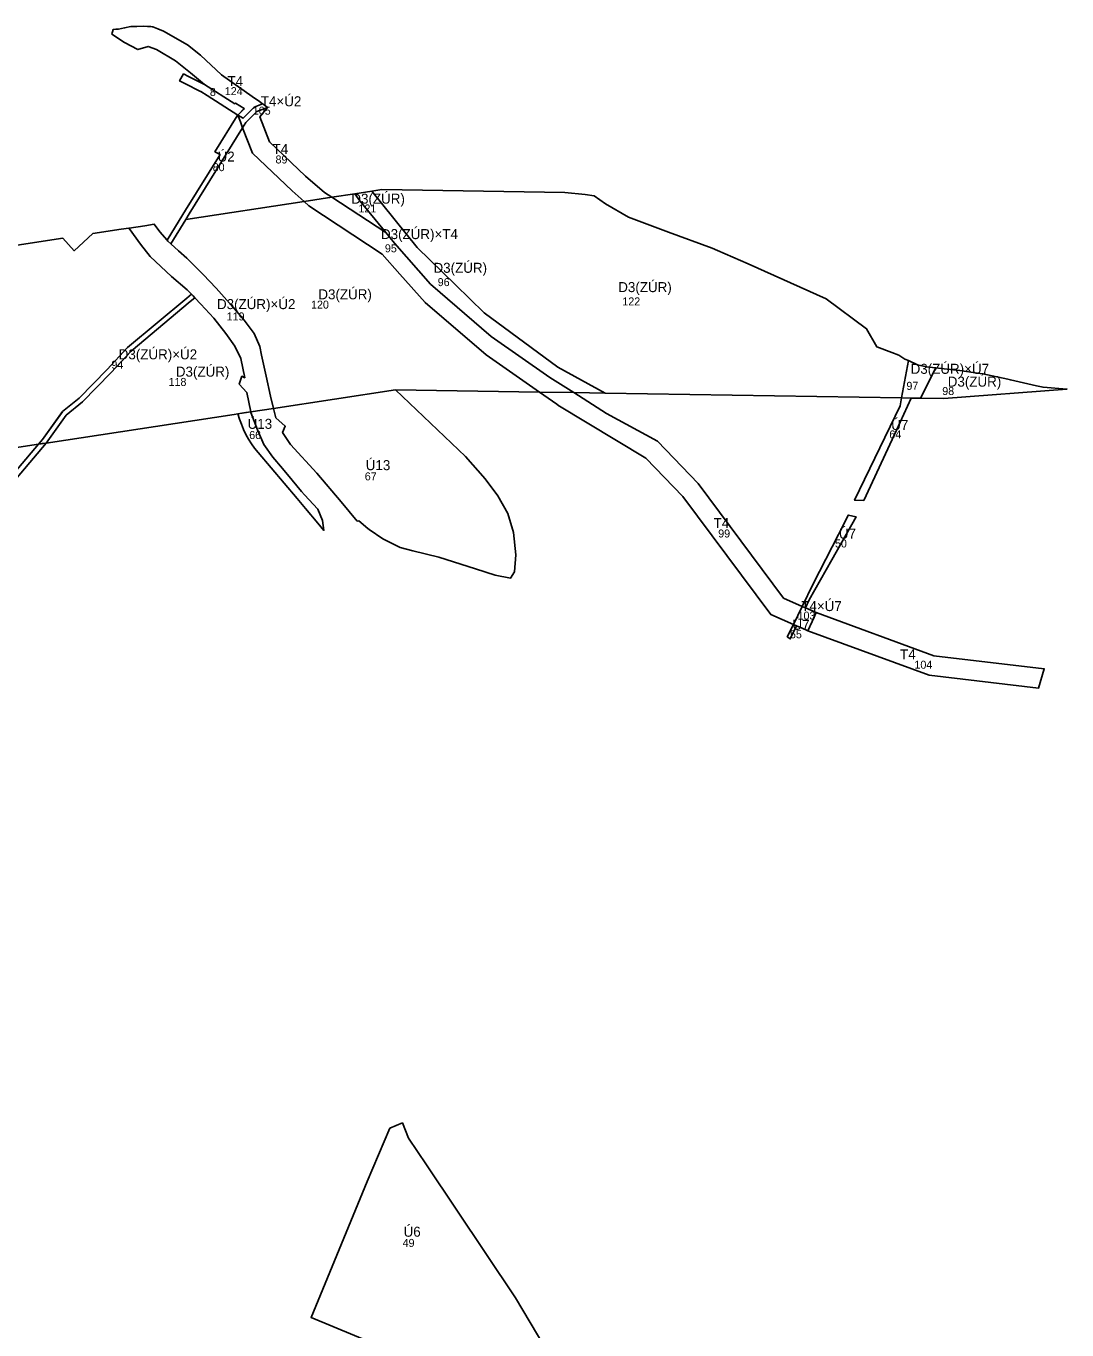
# Model space of a CAD drawing. Extents: x -521621 to -516857, y -1190025 to -1185894.
# Drawn here: x -518471 to -517431, y -1188636 to -1187332 of the extents above; entities that cross this region are included whole.
import ezdxf

# ---------------------------------------------------------------- set-up
doc = ezdxf.new("R2010")
doc.units = 0
for name, color, linetype in [('predk_pravo_n', 7, 'Continuous'), ('VPO_id', 7, 'Continuous'), ('VPO_n', 7, 'Continuous'), ('VPS_id', 7, 'Continuous'), ('VPS_n', 7, 'Continuous')]:
    doc.layers.add(name, color=color, linetype=linetype)

msp = doc.modelspace()

# ---------------------------------------------------------------- linework, layer by layer
at = {"layer": 'predk_pravo_n'}
msp.add_lwpolyline([(-518262.4, -1187410.1), (-518261.7, -1187409.4), (-518253.1, -1187414.9), (-518259.5, -1187421.5), (-518290.1, -1187402), (-518296.3, -1187398), (-518296.7, -1187397.8), (-518312.4, -1187389.9), (-518317.7, -1187387.2), (-518313.6, -1187380.3), (-518308.6, -1187382.8), (-518292.7, -1187390.8)], close=True, dxfattribs=at)
at = {"layer": 'VPO_n'}
msp.add_line((-518259.3, -1187720.1), (-518251.5, -1187718.9), dxfattribs=at)
for points in [[(-518256.9, -1187428.3), (-518259.5, -1187421.5), (-518260.1, -1187422.1), (-518282.4, -1187458), (-518277.2, -1187460.9), (-518311.7, -1187516.6), (-518318, -1187526.7), (-518330.2, -1187546.5), (-518329.5, -1187547.4), (-518326.5, -1187550.1), (-518311.5, -1187525.7), (-518308.1, -1187520.3), (-518254.7, -1187434.1), (-518256.9, -1187428.3)], [(-517981.5, -1187861.2), (-517984, -1187838.7), (-517989.8, -1187819.8), (-517999.6, -1187802), (-518012.2, -1187785.1), (-518031.8, -1187762.8), (-518102, -1187696.1), (-518223.7, -1187714.7), (-518221.4, -1187724), (-518212.1, -1187732.3), (-518214.8, -1187738.7), (-518206.7, -1187750.6), (-518180.6, -1187779.3), (-518156.2, -1187808.2), (-518140.1, -1187827.4), (-518138.5, -1187827.1), (-518129.6, -1187834.7), (-518128.2, -1187835.9), (-518114.6, -1187845), (-518097.1, -1187853.8), (-518084.7, -1187856.9), (-518058.6, -1187863.4), (-518021.9, -1187875.1), (-518002.4, -1187881.3), (-517987, -1187884.5), (-517982.9, -1187878.1), (-517981.5, -1187861.2)], [(-518251.5, -1187718.9), (-518246.6, -1187718.2), (-518246.4, -1187718.8), (-518239.9, -1187736), (-518233.5, -1187750.6), (-518224.4, -1187763.4), (-518214.8, -1187774.7), (-518205.2, -1187786.3), (-518195.8, -1187797.6), (-518192.9, -1187801.1), (-518179.6, -1187815.4), (-518174.7, -1187826.8), (-518173.4, -1187836.7), (-518179.5, -1187829.5), (-518191.9, -1187814.8), (-518200.3, -1187804.9), (-518239.2, -1187758.9)], [(-517695.5, -1187912.6), (-517684.5, -1187890.1), (-517652.7, -1187828.4), (-517649.4, -1187821.4), (-517641.6, -1187823), (-517665.7, -1187866.1), (-517688.4, -1187906.2), (-517692.2, -1187914)], [(-517692.2, -1187914), (-517695.5, -1187912.6)], [(-517701, -1187932), (-517707.4, -1187945.2), (-517710.4, -1187943), (-517704.3, -1187930.6)], [(-517704.3, -1187930.6), (-517701, -1187932)]]:
    msp.add_lwpolyline(points, dxfattribs=at)
for points in [[(-517633.7, -1187806.7), (-517643.1, -1187806.5), (-517597.6, -1187712.2), (-517596.1, -1187704.1), (-517586.4, -1187704.3), (-517601.2, -1187736.4)], [(-518451.1, -1187749.3), (-518518.3, -1187828.7), (-518530, -1187850.3), (-518533.4, -1187846), (-518522.5, -1187825.9), (-518458.6, -1187750.5)], [(-518107.5, -1188434.2), (-518094.9, -1188429), (-518088.8, -1188444.4), (-518071, -1188471), (-517982, -1188604), (-517899.2, -1188742.7), (-518042.7, -1188683.1), (-518186.2, -1188623.6), (-518130.3, -1188487.5)]]:
    msp.add_lwpolyline(points, close=True, dxfattribs=at)
msp.add_arc((-518164.4, -1187695.6), 98, 194.4563, 220.234, dxfattribs=at)
at = {"layer": 'VPS_n'}
for points in [[(-518306.6, -1187379.1), (-518292.7, -1187390.8), (-518262.4, -1187410.1), (-518261.7, -1187409.4), (-518253.1, -1187414.9), (-518253.9, -1187415.7), (-518259.5, -1187421.5), (-518254.2, -1187424.6), (-518248.7, -1187419), (-518243.2, -1187413.5), (-518234.7, -1187410.2), (-518237.9, -1187407.9), (-518245, -1187402.9), (-518275.7, -1187381.1), (-518296.7, -1187361.5), (-518309.7, -1187351.1), (-518333.6, -1187337.4), (-518339.3, -1187335.3), (-518344.5, -1187333.3), (-518345, -1187333.1), (-518346.4, -1187333), (-518349.6, -1187332.8), (-518354.1, -1187332.4), (-518360.3, -1187332.7), (-518366.5, -1187332.9), (-518372.6, -1187334.2), (-518378.8, -1187335.5), (-518381.4, -1187335.6), (-518384, -1187335.7), (-518384.7, -1187338.1), (-518385, -1187339.1), (-518385.4, -1187340.4), (-518372.8, -1187348.8), (-518359.5, -1187355.9), (-518349.2, -1187352.8), (-518340.9, -1187355.7), (-518321.7, -1187367.1), (-518306.6, -1187379.1)], [(-518240.4, -1187417.7), (-518229.8, -1187413.7), (-518232.2, -1187411.9), (-518234.7, -1187410.2), (-518243.2, -1187413.5), (-518248.7, -1187419), (-518254.2, -1187424.6), (-518259.5, -1187421.5), (-518256.9, -1187428.3), (-518254.7, -1187434.1), (-518251.4, -1187428.9), (-518244.4, -1187421.8), (-518240.4, -1187417.7)], [(-518240.4, -1187417.7), (-518244.4, -1187421.8), (-518251.4, -1187428.9), (-518254.7, -1187434.1), (-518244.8, -1187459.6), (-518205.2, -1187497.2), (-518193.2, -1187507.7), (-518165.5, -1187503.5), (-518172.9, -1187498.9), (-518191.7, -1187482.4), (-518227.7, -1187448.2), (-518237.5, -1187423), (-518229.8, -1187413.7), (-518240.4, -1187417.7)], [(-518223.7, -1187714.7), (-518102, -1187696.1), (-517958.1, -1187698.4), (-518011.3, -1187661), (-518072.1, -1187608.7), (-518097.5, -1187580.5), (-518115.1, -1187560.4), (-518188.5, -1187512.3), (-518193.2, -1187507.7), (-518311.5, -1187525.7), (-518326.5, -1187550.1), (-518318.7, -1187557.1), (-518310.4, -1187564.3), (-518294.1, -1187580.8), (-518281, -1187594.4), (-518267.8, -1187609.4), (-518266.5, -1187610.8), (-518253.1, -1187626.6), (-518243.1, -1187639.9), (-518237.5, -1187652.9), (-518235.9, -1187661.6), (-518231.2, -1187682.4), (-518226.7, -1187702.5), (-518223.7, -1187714.7)], [(-518142.6, -1187500), (-518165.5, -1187503.5), (-518111.5, -1187538.9), (-518137.5, -1187507.1), (-518142.6, -1187500)], [(-518142.6, -1187500), (-518137.5, -1187507.1), (-518111.5, -1187538.9), (-518102.9, -1187549.4), (-518067, -1187590.4), (-518006.3, -1187642.7), (-517947.8, -1187683.7), (-517923.8, -1187698.9), (-517892.4, -1187699.4), (-517939.8, -1187673.3), (-518013.4, -1187619.1), (-518042.1, -1187591.1), (-518080.2, -1187553.9), (-518125.5, -1187497.4), (-518142.6, -1187500)], [(-517939.8, -1187673.3), (-517892.4, -1187699.4), (-517596.1, -1187704.1), (-517589.2, -1187666.9), (-517592.8, -1187665.3), (-517598.9, -1187661.5), (-517606, -1187658.8), (-517620.9, -1187653.2), (-517631.2, -1187635), (-517671.4, -1187605.2), (-517749.3, -1187570.2), (-517780, -1187556.7), (-517785.5, -1187554.6), (-517829, -1187538.4), (-517869.1, -1187523.4), (-517892, -1187510.1), (-517903.3, -1187502.1), (-517912.3, -1187500.7), (-517932.8, -1187498.8), (-518115.5, -1187495.9), (-518125.5, -1187497.4), (-518080.2, -1187553.9), (-518042.1, -1187591.1), (-518013.4, -1187619.1), (-517939.8, -1187673.3)], [(-518614.8, -1187572), (-518434.3, -1187544.5), (-518423, -1187557), (-518404.5, -1187539.9), (-518376.1, -1187535.6), (-518368.5, -1187534.4), (-518367.9, -1187534.7), (-518356.8, -1187550.6), (-518347, -1187562.8), (-518336.4, -1187572.9), (-518325.6, -1187582.7), (-518310, -1187596), (-518305.9, -1187600.4), (-518310.5, -1187604.3), (-518369.6, -1187653.8), (-518390.1, -1187675.7), (-518418.1, -1187704.4), (-518434.6, -1187717.9), (-518454.6, -1187745.7), (-518458.6, -1187750.5), (-518594.2, -1187771.1)], [(-518318.7, -1187557.1), (-518326.5, -1187550.1), (-518329.5, -1187547.4), (-518330.2, -1187546.5), (-518337.4, -1187538), (-518343, -1187530.5), (-518352.3, -1187532), (-518368.1, -1187534.4), (-518367.9, -1187534.7), (-518356.8, -1187550.6), (-518347, -1187562.8), (-518336.4, -1187572.9), (-518325.6, -1187582.7), (-518310, -1187596), (-518305.9, -1187600.4), (-518304.1, -1187602.2), (-518302.4, -1187604), (-518296.4, -1187610.4), (-518283.6, -1187624.5), (-518271.6, -1187639.8), (-518262.3, -1187652.3), (-518256.3, -1187664.8), (-518252.6, -1187684.1), (-518255.4, -1187682.6), (-518258, -1187690.3), (-518250.4, -1187698.8), (-518246.6, -1187718.2), (-518223.7, -1187714.7), (-518226.7, -1187702.5), (-518231.2, -1187682.4), (-518235.9, -1187661.6), (-518237.5, -1187652.9), (-518243.1, -1187639.9), (-518253.1, -1187626.6), (-518266.5, -1187610.8), (-518267.8, -1187609.4), (-518281, -1187594.4), (-518294.1, -1187580.8), (-518310.4, -1187564.3), (-518318.7, -1187557.1)], [(-518302.4, -1187604), (-518307, -1187607.8), (-518366.2, -1187657.5), (-518386.5, -1187679.2), (-518414.8, -1187708.1), (-518430.9, -1187721.3), (-518451.1, -1187749.3), (-518322.2, -1187729.7), (-518263.2, -1187720.7), (-518259.3, -1187720.1), (-518246.6, -1187718.2), (-518250.4, -1187698.8), (-518258, -1187690.3), (-518255.4, -1187682.6), (-518252.6, -1187684.1), (-518256.3, -1187664.8), (-518262.3, -1187652.3), (-518271.6, -1187639.8), (-518283.6, -1187624.5), (-518296.4, -1187610.4), (-518302.4, -1187604)], [(-517586.4, -1187704.3), (-517596.1, -1187704.1), (-517589.2, -1187666.9), (-517580.3, -1187671.2), (-517573, -1187672.9), (-517572.6, -1187673), (-517572, -1187673.1)], [(-517562, -1187674.2), (-517577.2, -1187704.4)], [(-517562, -1187674.2), (-517577.2, -1187704.4), (-517553.8, -1187704.8), (-517430.9, -1187695.3), (-517454.8, -1187693.5), (-517461.3, -1187692.1), (-517487.3, -1187686.2), (-517489.9, -1187685.6), (-517514.8, -1187680), (-517520.3, -1187679.3), (-517520.3, -1187679.3), (-517537.9, -1187676.9), (-517553.7, -1187675.1), (-517562, -1187674.2)], [(-517572, -1187673.1), (-517562, -1187674.2)], [(-517940.8, -1187710.5), (-517958.1, -1187698.4), (-517923.8, -1187698.9), (-517890.9, -1187719.9)], [(-517577.2, -1187704.4), (-517586.4, -1187704.3)], [(-517704.3, -1187930.6), (-517726.9, -1187920.7), (-517814.6, -1187802.6), (-517851.6, -1187764.3), (-517939.7, -1187711.3)], [(-517890.9, -1187719.9), (-517840.1, -1187747.4), (-517799.3, -1187789.7), (-517714, -1187904.5), (-517695.5, -1187912.6)], [(-517695.5, -1187912.6), (-517704.3, -1187930.6)], [(-517689.8, -1187936.9), (-517568.5, -1187981.4), (-517459.3, -1187994.2), (-517453.5, -1187975), (-517563.8, -1187961.9), (-517681.4, -1187918.8), (-517685.6, -1187927.8), (-517689.8, -1187936.9)]]:
    msp.add_lwpolyline(points, dxfattribs=at)
for points in [[(-518193.2, -1187507.7), (-518165.5, -1187503.5), (-518111.5, -1187538.9), (-518102.9, -1187549.4), (-518067, -1187590.4), (-518006.3, -1187642.7), (-517947.8, -1187683.7), (-517923.8, -1187698.9), (-517958.1, -1187698.4), (-518011.3, -1187661), (-518072.1, -1187608.7), (-518097.5, -1187580.5), (-518115.1, -1187560.4), (-518188.5, -1187512.3)], [(-518434.6, -1187717.9), (-518418.1, -1187704.4), (-518390.1, -1187675.7), (-518369.6, -1187653.8), (-518310.5, -1187604.3), (-518305.9, -1187600.4), (-518304.1, -1187602.2), (-518302.4, -1187604), (-518307, -1187607.8), (-518366.2, -1187657.5), (-518386.5, -1187679.2), (-518414.8, -1187708.1), (-518430.9, -1187721.3), (-518451.1, -1187749.3), (-518454.9, -1187749.9), (-518458.6, -1187750.5), (-518454.6, -1187745.7), (-518434.6, -1187718)], [(-517704.3, -1187930.6), (-517695.5, -1187912.6), (-517692.2, -1187914), (-517681.4, -1187918.8), (-517685.6, -1187927.8), (-517689.8, -1187936.9), (-517695.4, -1187934.5), (-517701, -1187932)]]:
    msp.add_lwpolyline(points, close=True, dxfattribs=at)
msp.add_arc((-517929.3, -1187694.1), 20, 234.944, 238.9499, dxfattribs=at)

# ---------------------------------------------------------------- texts
at = {"layer": 'predk_pravo_n'}
msp.add_text('8', height=8, dxfattribs=at).set_placement((-518287.4, -1187402.3))
at = {"layer": 'VPO_id'}
for s, p in [('80', (-518284.6, -1187477.5)), ('66', (-518248.1, -1187745.3)), ('64', (-517608.4, -1187744.7)), ('67', (-518132.6, -1187786.6)), ('50', (-517662.7, -1187853.7)), ('55', (-517707.7, -1187944.5)), ('49', (-518094.8, -1188553))]:
    msp.add_text(s, height=8, dxfattribs=at).set_placement(p)
at = {"layer": 'VPO_n'}
for s, p in [('Ú2', (-518279.7, -1187467.9)), ('Ú13', (-518249.7, -1187735.1)), ('Ú7', (-517606.5, -1187736.3)), ('Ú13', (-518131.6, -1187776.4)), ('Ú7', (-517658.8, -1187844.9)), ('Ú7', (-517705.2, -1187936)), ('Ú6', (-518093.8, -1188542.8))]:
    msp.add_text(s, height=10, dxfattribs=at).set_placement(p)
at = {"layer": 'VPS_id'}
for s, p in [('124', (-518272.5, -1187401.5)), ('105', (-518244.5, -1187421)), ('89', (-518221.8, -1187469.8)), ('121', (-518138.9, -1187518.8)), ('95', (-518112.5, -1187558.6)), ('96', (-518059.7, -1187592.4)), ('120', (-518186.3, -1187614.9)), ('122', (-517875.2, -1187611.7)), ('119', (-518270.6, -1187626.7)), ('94', (-518385.8, -1187675)), ('118', (-518328.7, -1187692.2)), ('97', (-517591.3, -1187696.1)), ('98', (-517555.5, -1187701.3)), ('99', (-517779.4, -1187843.7)), ('103', (-517700.1, -1187925.8)), ('104', (-517583.3, -1187974.9))]:
    msp.add_text(s, height=8, dxfattribs=at).set_placement(p)
at = {"layer": 'VPS_n'}
for s, p in [('T4', (-518269.8, -1187392.5)), ('T4×Ú2', (-518236.5, -1187412.6)), ('T4', (-518224.7, -1187460.3)), ('D3(ZÚR)', (-518146, -1187510)), ('D3(ZÚR)×T4', (-518116.4, -1187545.4)), ('D3(ZÚR)', (-518063.9, -1187579.1)), ('D3(ZÚR)', (-517879.3, -1187598.4)), ('D3(ZÚR)', (-518179, -1187605.6)), ('D3(ZÚR)×Ú2', (-518280.3, -1187615.4)), ('D3(ZÚR)×Ú2', (-518378.5, -1187665.6)), ('D3(ZÚR)', (-518321.4, -1187682.9)), ('D3(ZÚR)×Ú7', (-517587.1, -1187680.1)), ('D3(ZÚR)', (-517550, -1187692.9)), ('T4', (-517784, -1187834.3)), ('T4×Ú7', (-517696.4, -1187917.3)), ('T4', (-517597.7, -1187965.6))]:
    msp.add_text(s, height=10, dxfattribs=at).set_placement(p)

doc.saveas('drawing.dxf')
